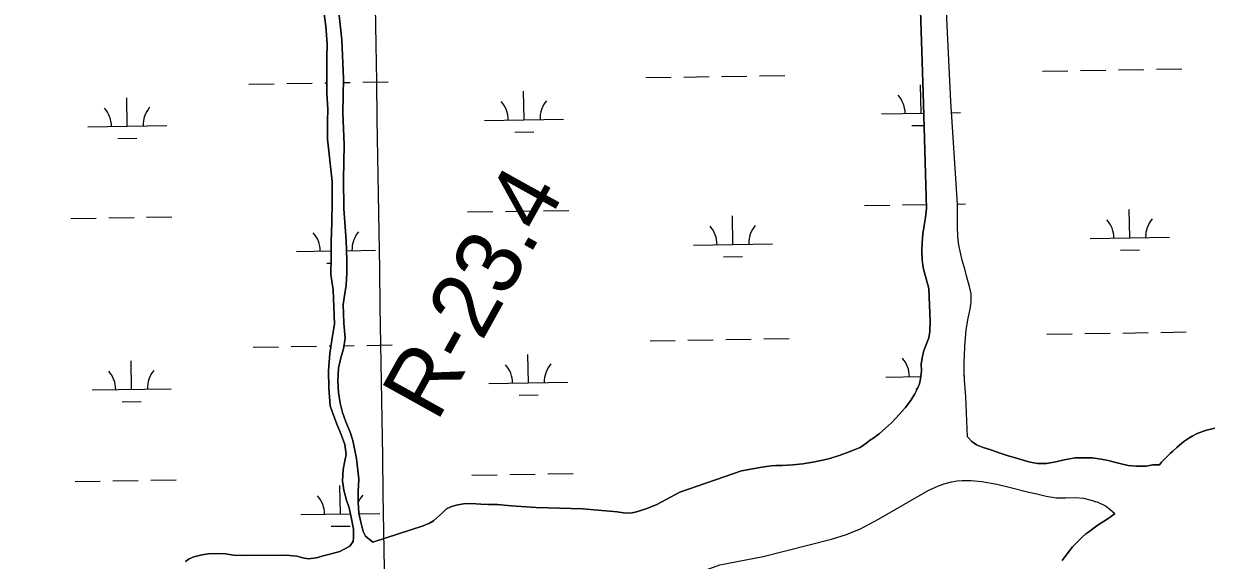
# Model space of a CAD drawing. Extents: x 3855477 to 3893699, y 299188 to 325115.
# Drawn here: x 3864404 to 3865905, y 316217 to 316895 of the extents above; entities that cross this region are included whole.
import ezdxf

# ---------------------------------------------------------------- set-up
doc = ezdxf.new("R2010")
doc.units = 0
for name, color, linetype in [('V-GRID-MAJR', 7, 'Continuous'), ('V-RIVR-EDGE', 7, 'Continuous'), ('V-RIVR-RANG-IDEN', 7, 'Continuous'), ('V-TOPO-SHOR', 7, 'Continuous'), ('V-WETL-SWMP', 7, 'Continuous')]:
    doc.layers.add(name, color=color, linetype=linetype)

msp = doc.modelspace()

# ---------------------------------------------------------------- linework, layer by layer
at = {"layer": 'V-GRID-MAJR'}
msp.add_spline([(3865044.1, 304703.3), (3864995.7, 307731.4), (3864898.7, 313791.5), (3864801.7, 319851.5), (3864753.2, 322883.5)], degree=3, dxfattribs=at)
at = {"layer": 'V-RIVR-EDGE'}
msp.add_spline([(3862579.1, 316706.6), (3862618.9, 316682.6), (3862652.8, 316666.1), (3862683, 316656.5), (3862696.2, 316652.9), (3862701.3, 316646.9), (3862715.3, 316640.1), (3862730, 316634.5), (3862738.8, 316633.6), (3862748.3, 316626.1), (3862763.5, 316620.4), (3862771, 316614.8), (3862792.5, 316606), (3862806.8, 316598.8), (3862818, 316594.4), (3862834.3, 316586.8), (3862853, 316578.4), (3862861.8, 316570.8), (3862880.1, 316564.8), (3862890, 316564.7), (3862900, 316564.3), (3862907.6, 316561.5), (3862923.9, 316554.7), (3862944.6, 316544.7), (3862975.6, 316529), (3863008.7, 316511), (3863036.9, 316493.4), (3863051.3, 316484.2), (3863059.6, 316479.8), (3863073.1, 316469.4), (3863078.7, 316461.8), (3863091, 316455.4), (3863113.7, 316446.6), (3863137.2, 316440.6), (3863166.3, 316430.5), (3863183.4, 316425.7), (3863207.7, 316412.1), (3863228, 316399.7), (3863238.3, 316395.7), (3863252.7, 316390.5), (3863259.4, 316385.3), (3863266.6, 316378.1), (3863269.4, 316370.9), (3863279.3, 316363.3), (3863294.4, 316355.7), (3863309.2, 316346.9), (3863343, 316331.3), (3863355.3, 316322.1), (3863380.4, 316304.5), (3863423.4, 316277.3), (3863452, 316258.5), (3863472.7, 316247.6), (3863532.4, 316214.8), (3863576.2, 316192.8), (3863612, 316174), (3863663, 316147.9), (3863702, 316129.9), (3863762.1, 316101.5), (3863803.5, 316080.6), (3863847.7, 316056.6), (3863876.3, 316044.2), (3863896.6, 316031.8), (3863917.7, 316020.6), (3863971.8, 315991.3), (3864020.8, 315966.1), (3864054.2, 315946.5), (3864091.6, 315926.9), (3864114.7, 315913.7), (3864131.9, 315906.9), (3864147, 315897.7), (3864174, 315883.6), (3864183.2, 315874.1), (3864194.3, 315870.4), (3864207.5, 315866.8), (3864224.2, 315858.8), (3864239.3, 315850.4), (3864262.4, 315840), (3864273.6, 315837.2), (3864288.7, 315830.4), (3864303.8, 315827.9), (3864315.4, 315825.1), (3864338.5, 315817.1), (3864360.8, 315810.6), (3864391.4, 315792.2), (3864418.9, 315776.2), (3864436, 315762.2), (3864459, 315741.9), (3864510.4, 315709.8), (3864535.4, 315695.8), (3864549, 315685.4), (3864561.3, 315675.8), (3864568.8, 315666.7), (3864582.4, 315656.7), (3864595.1, 315647.1), (3864600.7, 315641.1), (3864607, 315633.1), (3864612.6, 315626.3), (3864620.2, 315622.7), (3864637.3, 315615.9), (3864659.6, 315609), (3864678.3, 315601), (3864697.4, 315595.4), (3864745.6, 315571.8), (3864769.9, 315563.7), (3864787.4, 315555.7), (3864811.2, 315540.5), (3864821.2, 315537.7), (3864833.2, 315537.7), (3864842.3, 315536.5), (3864849.5, 315531.3), (3864857.4, 315522.9), (3864872.2, 315516.9), (3864908, 315506), (3864925.1, 315500.4), (3864937.9, 315498.8), (3864948.6, 315491.6), (3864957, 315489.5), (3864964.2, 315487.5), (3865017.5, 315468.3), (3865068.5, 315449.8), (3865096.3, 315439.4), (3865128.6, 315425), (3865154.9, 315414.9), (3865176, 315401.7), (3865212.2, 315385.7), (3865243.6, 315368.5), (3865263.1, 315356.5), (3865277.9, 315348.1), (3865297, 315338.1), (3865316.5, 315331.2), (3865337.2, 315318), (3865369.4, 315298.4), (3865405.2, 315275.2), (3865431.9, 315259.6), (3865448.2, 315254), (3865473.7, 315238.4), (3865499.1, 315224.8), (3865515.1, 315218), (3865531.8, 315209.2), (3865549.7, 315199.5), (3865571.2, 315191.5), (3865609, 315173.1), (3865654, 315145.5), (3865693.8, 315123.1), (3865732.8, 315101.8), (3865776.9, 315077.4), (3865798.4, 315063.8), (3865826.7, 315046.6), (3865853.4, 315032.6), (3865883.2, 315017.4), (3865895.1, 315011.4), (3865904.3, 315003.8), (3865913, 314994.6), (3865919.8, 314990.2), (3865927.8, 314987.4), (3865939.7, 314983.4), (3865950.5, 314980.6), (3865961.6, 314976.5), (3865977.5, 314967.3), (3866028.9, 314942.9), (3866056.7, 314928.5), (3866076.6, 314915.3), (3866096.5, 314901.7), (3866120.4, 314888.5), (3866143.9, 314878.1), (3866161.4, 314867.2), (3866178.1, 314862.8), (3866201.2, 314856.8), (3866223.1, 314850.4), (3866245.8, 314837.5), (3866263.7, 314827.1), (3866282.8, 314818.7), (3866292.4, 314818.7), (3866300.8, 314818.3), (3866309.9, 314816.3), (3866326.7, 314808.7), (3866348.5, 314791.1), (3866360.1, 314786.3), (3866377.6, 314778.6), (3866387.5, 314775), (3866394.3, 314767.4), (3866401.9, 314762.2), (3866413.8, 314757), (3866423.4, 314751.4), (3866432.1, 314749.8), (3866437.7, 314746.2), (3866445.6, 314739.4), (3866454.4, 314732.2), (3866485.5, 314719), (3866510.5, 314708.6), (3866533.2, 314691.4), (3866542, 314691.3), (3866549.9, 314690.9), (3866556.3, 314686.5), (3866561.9, 314678.5), (3866573.8, 314670.1), (3866598.9, 314663.7), (3866631.1, 314649.3), (3866660.6, 314640.4), (3866694.9, 314628.4), (3866748.2, 314604.4), (3866780.4, 314591.5), (3866811.1, 314575.5), (3866846.9, 314561.5), (3866895.5, 314539), (3866932.1, 314524.6), (3866954.8, 314513.4), (3866988.3, 314500.5), (3867018.5, 314486.5), (3867041.2, 314475.3), (3867068.7, 314458.5), (3867097.3, 314440.1), (3867124, 314432.5), (3867147.1, 314433.2), (3867169.4, 314428), (3867197.3, 314417.1), (3867215.2, 314410.7), (3867238.7, 314401.5), (3867251.4, 314396.3), (3867258.6, 314395.9), (3867271.4, 314397.4), (3867288.1, 314397.8), (3867302.4, 314396.1), (3867345.5, 314385.3), (3867427.5, 314359.6), (3867438.3, 314357.9), (3867445, 314357.9), (3867453.4, 314369.5), (3867458.2, 314381.4), (3867462.3, 314395.8), (3867462.3, 314404.1), (3867460.7, 314411.7), (3867457.1, 314414.1), (3867450.8, 314416.1), (3867442.8, 314416.5), (3867438.8, 314420.1), (3867443.2, 314422.1), (3867451.6, 314428.1), (3867458.8, 314437.2), (3867459.6, 314442.8), (3867460, 314450.8), (3867463.6, 314455.1), (3867470.8, 314463.9), (3867472, 314469.5), (3867472.4, 314477), (3867471.6, 314485), (3867465.7, 314504.5), (3867463.7, 314514.5), (3867463.4, 314524.5), (3867464.2, 314541.2), (3867469.1, 314571.1), (3867474.7, 314579.8), (3867478.3, 314581.4), (3867485, 314582.6), (3867525.3, 314574.9), (3867536, 314568.9), (3867545.2, 314565.7), (3867555.1, 314566.5), (3867569.9, 314566.1), (3867581, 314559.7), (3867585, 314552.1), (3867591.7, 314543.7), (3867611.6, 314532.9), (3867628, 314518.1), (3867650.2, 314493.3), (3867659.8, 314484.9), (3867663.3, 314473), (3867663.3, 314455.4), (3867660.1, 314447.5), (3867647.3, 314446.3), (3867632.2, 314444.7), (3867612.6, 314438.4), (3867582.3, 314425.3)], degree=3, dxfattribs=at)
at = {"layer": 'V-TOPO-SHOR'}
msp.add_line((3864836.2, 316247.2), (3864845.1, 316239.5), dxfattribs=at)
for points in [[(3865363.1, 316336.3), (3865376.5, 316337.2), (3865388.9, 316338.7), (3865401.8, 316340.6), (3865412.1, 316342.9), (3865423, 316345.4), (3865436.4, 316349.6), (3865447.8, 316353.6), (3865461.7, 316359.3), (3865469.8, 316365), (3865473.3, 316367.9), (3865478.8, 316371.6), (3865485.7, 316376.7), (3865493.7, 316383.5), (3865501, 316390.4), (3865507, 316396.8), (3865514.2, 316404.8), (3865518.8, 316409.7), (3865525.9, 316419.7), (3865530.8, 316427.2), (3865533.6, 316432.8), (3865536.5, 316439.8), (3865537.9, 316445.9), (3865539, 316456), (3865538.8, 316464.8), (3865540.1, 316472.7), (3865542, 316481.9), (3865545.4, 316490.5), (3865548.3, 316497.7), (3865549.5, 316506.1), (3865549.9, 316518.6), (3865548.2, 316560.1), (3865545, 316572.5), (3865541.4, 316586.5), (3865539.9, 316596.5), (3865539.6, 316607.9), (3865539.8, 316618.2), (3865540.8, 316629.4), (3865542.5, 316639.8), (3865544.2, 316650), (3865545.6, 316661.5), (3865541.4, 316808.2), (3865536.3, 316963.5)], [(3865597.2, 316372.9), (3865595.2, 316423.3), (3865593.6, 316444.5), (3865592.9, 316453.7), (3865592.9, 316466.7), (3865593.5, 316475.2), (3865593.7, 316487), (3865595.4, 316508.1), (3865598.3, 316522.9), (3865600.8, 316534.3), (3865601.9, 316543.2), (3865601.8, 316553.5), (3865599.7, 316563), (3865596.6, 316574.4), (3865593.7, 316585.3), (3865591.1, 316594.5), (3865589, 316603.6), (3865586.4, 316614.9), (3865585.2, 316625.7), (3865584.6, 316639), (3865584.6, 316666.9), (3865576.1, 316796.7), (3865568.8, 316954.4)], [(3864800.8, 316924.8), (3864806.3, 316874.8), (3864808.1, 316825.7), (3864807.3, 316782.5), (3864808.9, 316742.5), (3864808.6, 316719.6), (3864808.4, 316699), (3864808.8, 316660.9), (3864811.6, 316620.9), (3864812.5, 316596), (3864812.3, 316580.1), (3864811.4, 316564.7), (3864809.7, 316554), (3864807.6, 316540.2), (3864808.5, 316516.4), (3864810.3, 316497.4), (3864808.2, 316483.9), (3864804.9, 316472.5), (3864802, 316459.4), (3864801, 316443.6), (3864801.7, 316428.9), (3864803.9, 316415.5), (3864807, 316403.5), (3864811.2, 316391.6), (3864816.6, 316378.5), (3864820, 316368.2), (3864824.6, 316345.5), (3864827.5, 316319.4), (3864826.9, 316303.5), (3864826.8, 316290.1), (3864827.8, 316276.2), (3864830.1, 316264.7), (3864833.1, 316253.2), (3864836.2, 316247.2)], [(3864803.4, 316227.8), (3864816.1, 316234.4), (3864820.5, 316240.3), (3864821, 316245.5), (3864820.7, 316255.8), (3864818.5, 316268.9), (3864815.4, 316282.8), (3864812, 316292.7), (3864808.5, 316305.4), (3864807.1, 316317.3), (3864807.6, 316331.6), (3864810.1, 316342.6), (3864811.4, 316350.5), (3864809.9, 316363.2), (3864805.3, 316375.5), (3864799.9, 316388.7), (3864793.7, 316404.6), (3864791.4, 316412.1), (3864789.7, 316434.7), (3864789.1, 316456.1), (3864790.9, 316477.9), (3864793.5, 316494.9), (3864796.8, 316515.8), (3864795.3, 316558.6), (3864792.3, 316578), (3864792.6, 316599), (3864792.8, 316618.8), (3864793.4, 316643.8), (3864793.7, 316670.7), (3864794, 316695.7), (3864787.8, 316749.2), (3864788, 316772.2), (3864788.2, 316786.8), (3864787.2, 316807.4), (3864787, 316830.4), (3864787.2, 316851.4), (3864787.4, 316869.6), (3864785.7, 316891.8), (3864783.5, 316910.4)], [(3865597.2, 316372.9), (3865602.9, 316366.7), (3865608.7, 316362.5), (3865617.1, 316359.4), (3865626.7, 316356.1), (3865637.2, 316352.4), (3865648.6, 316348.9), (3865657.8, 316346), (3865666, 316343.6), (3865676.3, 316340.7), (3865685.9, 316338.9), (3865697.3, 316339.2), (3865708.8, 316341.3), (3865719.6, 316343.7), (3865733.5, 316346), (3865745, 316346.2), (3865754.9, 316346.1), (3865766.2, 316344.7), (3865775.2, 316342.9), (3865783.1, 316340.7), (3865791.7, 316338.4), (3865800.3, 316336.6), (3865810.8, 316335.6), (3865823, 316335.8), (3865831.7, 316337.2), (3865840.2, 316337.4)], [(3865840.2, 316337.4), (3865842.6, 316340.7), (3865846.7, 316345.1), (3865849.6, 316347.9), (3865853.9, 316352.2), (3865857.1, 316354.8), (3865861.8, 316359.4), (3865865.4, 316362.3), (3865871, 316366.8), (3865877.1, 316371.2), (3865881.3, 316373.6), (3865887.6, 316376.8), (3865895.8, 316379.7), (3865899.6, 316381), (3865904.9, 316382.4), (3865910.2, 316383.7)], [(3864845.1, 316239.5), (3864909.1, 316260.2), (3864917.1, 316263.6), (3864922.1, 316266.4), (3864933.7, 316277.1), (3864938.5, 316281.7), (3864943.9, 316284.2), (3864950.8, 316286.2), (3864959.8, 316288.1), (3864969.3, 316288.6), (3864981.9, 316287.8), (3864991.7, 316287.2), (3865003.1, 316287.4), (3865020.4, 316285.6), (3865052, 316283.6), (3865111, 316281.8), (3865154.1, 316277.9), (3865162.1, 316276.5), (3865166.8, 316276.2), (3865173.1, 316276.7), (3865178.9, 316277.9), (3865185.6, 316279.9), (3865192.9, 316282.4), (3865204.5, 316287.3), (3865233.3, 316302.6), (3865311.5, 316329.7), (3865337.2, 316334.4), (3865349.2, 316336.2), (3865354.8, 316336.4), (3865363.1, 316336.3)], [(3865547.4, 316304.8), (3865560.4, 316310.7), (3865569.1, 316313.8), (3865577.2, 316315.9), (3865584, 316317), (3865590.6, 316317.7), (3865601.7, 316317.7), (3865615.2, 316316.1), (3865634.5, 316313.1), (3865651.6, 316308.8), (3865675, 316302.9), (3865684.9, 316300.5), (3865696.9, 316297.6), (3865709.9, 316295.8), (3865721.3, 316295.8), (3865733.4, 316295.9), (3865743.9, 316295), (3865753.8, 316292.7), (3865761.9, 316290), (3865771.6, 316285.5), (3865777.4, 316281.4), (3865783.6, 316275.7)], [(3865196, 316176.5), (3865249.6, 316198.2), (3865283.9, 316210.8), (3865338.8, 316221.4), (3865425.3, 316243.4), (3865444.1, 316249.4), (3865454.5, 316253.6), (3865461.1, 316256.2), (3865467.4, 316259.3), (3865484.6, 316268.6), (3865547.4, 316304.8)], [(3865717.1, 316216.4), (3865720.6, 316221.5), (3865723.2, 316224.9), (3865727.3, 316230.3), (3865730.2, 316233.8), (3865735.1, 316238.9), (3865738.4, 316242), (3865741.9, 316245.3), (3865747.1, 316250.1), (3865750.8, 316252.6), (3865755.9, 316256.5), (3865759.3, 316259.1), (3865764.9, 316263), (3865769.1, 316265.8), (3865775, 316269.5), (3865778.9, 316271.9), (3865783.6, 316275.7)], [(3864608.3, 316215), (3864612.9, 316218.4), (3864618.9, 316221.1), (3864629.2, 316223.4), (3864637.5, 316224.9), (3864647.4, 316225.4), (3864659.2, 316224.8), (3864669.3, 316223.3), (3864680.4, 316222.6), (3864735.4, 316223.1), (3864749.1, 316221.9)], [(3864749.1, 316221.9), (3864756.8, 316219.7), (3864763.5, 316218.7), (3864774, 316219.8), (3864782.5, 316222.1), (3864792.5, 316224.8), (3864803.4, 316227.8)]]:
    msp.add_lwpolyline(points, dxfattribs=at)
at = {"layer": 'V-WETL-SWMP'}
for p, q in [((3865190.4, 316826.9), (3865222.4, 316827.4)), ((3865238.4, 316827.6), (3865270.4, 316828.2)), ((3865286.4, 316828.4), (3865318.4, 316828.9)), ((3865334.4, 316829.2), (3865366.4, 316829.7)), ((3865692.2, 316835), (3865724.2, 316835.6)), ((3865740.2, 316835.8), (3865772.2, 316836.3)), ((3865788.2, 316836.6), (3865820.2, 316837.1)), ((3865836.2, 316837.4), (3865868.2, 316837.9)), ((3864688.5, 316818.7), (3864720.5, 316819.2)), ((3864736.5, 316819.5), (3864768.5, 316820)), ((3864784.5, 316820.2), (3864787.1, 316820.3)), ((3864808, 316820.6), (3864816.5, 316820.8)), ((3864832.5, 316821), (3864864.5, 316821.5)), ((3865036.6, 316773.6), (3865036, 316809.6)), ((3865538.5, 316781.8), (3865537.9, 316817.8)), ((3864534.8, 316765.4), (3864534.2, 316801.4)), ((3865488.5, 316781), (3865542.1, 316781.8)), ((3865577.1, 316782.4), (3865588.5, 316782.6)), ((3864484.8, 316764.6), (3864584.8, 316766.2)), ((3864986.6, 316772.8), (3865086.6, 316774.4)), ((3865526.7, 316766.2), (3865542.6, 316766.4)), ((3864523, 316749.8), (3864547, 316750.2)), ((3865024.9, 316758), (3865048.9, 316758.4)), ((3865013.1, 316657.8), (3865045.1, 316658.3)), ((3865061.1, 316658.6), (3865093.1, 316659.1)), ((3865467, 316665.2), (3865499, 316665.7)), ((3865514.9, 316665.9), (3865545.5, 316666.4)), ((3865584.6, 316667.1), (3865594.9, 316667.3)), ((3865802.5, 316624.2), (3865801.9, 316660.2)), ((3864463.3, 316648.8), (3864495.3, 316649.3)), ((3864511.3, 316649.6), (3864543.3, 316650.1)), ((3864559.3, 316650.4), (3864591.3, 316650.9)), ((3864965.1, 316657), (3864997.1, 316657.5)), ((3865300.7, 316616), (3865300.1, 316652)), ((3865250.7, 316615.2), (3865350.7, 316616.8)), ((3865752.5, 316623.4), (3865852.5, 316625)), ((3864748.8, 316607), (3864792.6, 316607.7)), ((3864812.1, 316608.1), (3864848.8, 316608.7)), ((3865288.9, 316600.4), (3865312.9, 316600.8)), ((3865790.8, 316608.6), (3865814.8, 316609)), ((3864787.1, 316592.2), (3864792.5, 316592.3)), ((3865195.8, 316494.2), (3865227.8, 316494.7)), ((3865243.8, 316495), (3865275.8, 316495.5)), ((3865291.8, 316495.8), (3865323.8, 316496.3)), ((3865339.8, 316496.6), (3865371.8, 316497.1)), ((3865697.6, 316502.4), (3865729.6, 316502.9)), ((3865745.6, 316503.2), (3865777.6, 316503.7)), ((3865793.6, 316504), (3865825.6, 316504.5)), ((3865841.6, 316504.7), (3865873.6, 316505.3)), ((3864694, 316486.1), (3864726, 316486.6)), ((3864742, 316486.8), (3864773.9, 316487.4)), ((3864789.9, 316487.6), (3864792.4, 316487.7)), ((3864808.8, 316487.9), (3864821.9, 316488.1)), ((3864837.9, 316488.4), (3864869.9, 316488.9)), ((3865543.3, 316485.1), (3865543.3, 316485.1)), ((3864540.2, 316432.8), (3864539.6, 316468.8)), ((3865042.1, 316441), (3865041.5, 316477)), ((3865493.9, 316448.3), (3865538.3, 316449.1)), ((3865593.2, 316450), (3865593.9, 316450)), ((3864490.2, 316432), (3864590.2, 316433.6)), ((3864992.1, 316440.2), (3865092, 316441.8)), ((3865532.1, 316433.5), (3865533.9, 316433.6)), ((3865030.3, 316425.3), (3865054.3, 316425.7)), ((3864528.5, 316417.2), (3864552.5, 316417.6)), ((3864468.7, 316316.2), (3864500.7, 316316.7)), ((3864516.7, 316317), (3864548.7, 316317.5)), ((3864564.7, 316317.8), (3864596.7, 316318.3)), ((3864970.5, 316324.4), (3865002.5, 316324.9)), ((3865018.5, 316325.1), (3865050.5, 316325.7)), ((3865066.5, 316325.9), (3865098.5, 316326.4)), ((3864804.3, 316275.2), (3864803.7, 316311.2)), ((3865757.9, 316290.8), (3865759.5, 316290.8)), ((3864754.3, 316274.4), (3864817, 316275.4)), ((3864827.9, 316275.6), (3864854.2, 316276)), ((3864792.5, 316259.6), (3864816.5, 316260))]:
    msp.add_line(p, q, dxfattribs=at)
for points in [[(3865536.3, 316963.5), (3865541.4, 316808.2), (3865545.6, 316661.5), (3865544.2, 316650), (3865542.5, 316639.8), (3865540.8, 316629.4), (3865539.8, 316618.2), (3865539.6, 316607.9), (3865539.9, 316596.5), (3865541.4, 316586.5), (3865545, 316572.5), (3865548.2, 316560.1), (3865549.9, 316518.6), (3865549.5, 316506.1), (3865548.3, 316497.7), (3865545.4, 316490.5), (3865542, 316481.9), (3865540.1, 316472.7), (3865538.8, 316464.8), (3865539, 316456), (3865537.9, 316445.9), (3865536.5, 316439.8), (3865533.6, 316432.8), (3865530.8, 316427.2), (3865525.9, 316419.7), (3865518.8, 316409.7), (3865514.2, 316404.8), (3865507, 316396.8), (3865501, 316390.4), (3865493.7, 316383.5), (3865485.7, 316376.7), (3865478.8, 316371.6), (3865473.3, 316367.9), (3865469.8, 316365), (3865461.7, 316359.3), (3865447.8, 316353.6), (3865436.4, 316349.6), (3865423, 316345.4), (3865412.1, 316342.9), (3865401.8, 316340.6), (3865388.9, 316338.7), (3865376.5, 316337.2), (3865363.1, 316336.3), (3865354.8, 316336.4), (3865349.2, 316336.2), (3865337.2, 316334.4), (3865311.5, 316329.7), (3865233.3, 316302.6), (3865204.5, 316287.3), (3865192.9, 316282.4), (3865185.6, 316279.9), (3865178.9, 316277.9), (3865173.1, 316276.7), (3865166.8, 316276.2), (3865162.1, 316276.5), (3865154.1, 316277.9), (3865111, 316281.8), (3865052, 316283.6), (3865020.4, 316285.6), (3865003.1, 316287.4), (3864991.7, 316287.2), (3864981.9, 316287.8), (3864969.3, 316288.6), (3864959.8, 316288.1), (3864950.8, 316286.2), (3864943.9, 316284.2), (3864938.5, 316281.7), (3864933.7, 316277.1), (3864922.1, 316266.4), (3864917.1, 316263.6), (3864909.1, 316260.2), (3864845.1, 316239.5), (3864836.2, 316247.2), (3864833.1, 316253.2), (3864830.1, 316264.7), (3864827.8, 316276.2), (3864826.8, 316290.1), (3864826.9, 316303.5), (3864827.5, 316319.4), (3864824.6, 316345.5), (3864820.1, 316368.2), (3864816.6, 316378.5), (3864811.2, 316391.6), (3864807, 316403.5), (3864803.9, 316415.5), (3864801.7, 316428.9), (3864801, 316443.6), (3864802, 316459.4), (3864804.9, 316472.5), (3864808.2, 316483.9), (3864810.3, 316497.4), (3864808.5, 316516.4), (3864807.6, 316540.2), (3864809.7, 316554), (3864811.4, 316564.7), (3864812.3, 316580.1), (3864812.5, 316596), (3864811.6, 316620.9), (3864808.8, 316660.9), (3864808.4, 316699)], [(3865666, 316343.6), (3865657.8, 316346), (3865648.6, 316348.9), (3865637.2, 316352.4), (3865626.7, 316356.1), (3865617.1, 316359.4), (3865608.7, 316362.5), (3865602.9, 316366.7), (3865597.2, 316372.9), (3865595.2, 316423.3), (3865593.6, 316444.5), (3865592.9, 316453.7), (3865592.9, 316466.7), (3865593.5, 316475.2), (3865593.7, 316487), (3865595.4, 316508.1), (3865598.3, 316522.9), (3865600.8, 316534.3), (3865601.9, 316543.2), (3865601.8, 316553.5), (3865599.7, 316563), (3865596.6, 316574.4), (3865593.7, 316585.3), (3865591.1, 316594.5), (3865589, 316603.6), (3865586.4, 316614.9), (3865585.2, 316625.7), (3865584.6, 316639), (3865584.6, 316666.9), (3865576.1, 316796.7), (3865568.8, 316954.4)], [(3864808.4, 316699), (3864808.6, 316719.6), (3864808.9, 316742.5), (3864807.3, 316782.5), (3864808.1, 316825.7), (3864806.3, 316874.8), (3864800.8, 316924.8)], [(3864783.5, 316910.4), (3864785.7, 316891.8), (3864787.4, 316869.6), (3864787.2, 316851.4), (3864787, 316830.4), (3864787.2, 316807.4), (3864788.2, 316786.8), (3864788, 316772.2), (3864787.8, 316749.2), (3864794, 316695.7), (3864793.7, 316670.7), (3864793.4, 316643.8), (3864792.8, 316618.8), (3864792.6, 316599), (3864792.3, 316578), (3864795.3, 316558.6), (3864796.8, 316515.8), (3864793.5, 316494.9), (3864790.9, 316477.9), (3864789.1, 316456.1), (3864789.7, 316434.7), (3864791.4, 316412.1), (3864793.7, 316404.6), (3864799.9, 316388.7), (3864805.3, 316375.5), (3864809.9, 316363.2), (3864811.4, 316350.5), (3864810.1, 316342.6), (3864807.6, 316331.6), (3864807.1, 316317.3), (3864808.5, 316305.4), (3864812, 316292.7), (3864815.4, 316282.8), (3864818.5, 316268.9), (3864820.7, 316255.8), (3864821, 316245.5), (3864820.5, 316240.3), (3864816.1, 316234.4), (3864803.4, 316227.8), (3864792.5, 316224.8), (3864782.5, 316222.1), (3864774, 316219.8), (3864763.5, 316218.7), (3864756.8, 316219.7), (3864749.1, 316221.9), (3864735.4, 316223.1), (3864680.4, 316222.6), (3864669.3, 316223.3), (3864659.2, 316224.8), (3864647.4, 316225.4), (3864637.5, 316224.9)], [(3865910.2, 316383.7), (3865904.9, 316382.4), (3865899.6, 316381), (3865895.8, 316379.7), (3865887.6, 316376.8), (3865881.3, 316373.6), (3865877.1, 316371.2), (3865871, 316366.8), (3865865.4, 316362.3), (3865861.8, 316359.4), (3865857.1, 316354.8), (3865853.9, 316352.2), (3865849.6, 316347.9), (3865846.7, 316345.1), (3865842.6, 316340.7), (3865840.2, 316337.4), (3865831.7, 316337.2), (3865823, 316335.8), (3865810.8, 316335.6), (3865800.3, 316336.6), (3865791.7, 316338.4), (3865783.1, 316340.7), (3865775.2, 316342.9), (3865766.2, 316344.7), (3865754.9, 316346.1), (3865745, 316346.2), (3865733.5, 316346), (3865719.6, 316343.7), (3865708.8, 316341.3), (3865697.3, 316339.2), (3865685.9, 316338.9), (3865676.3, 316340.7), (3865666, 316343.6)], [(3865283.9, 316210.8), (3865338.8, 316221.4), (3865425.3, 316243.4), (3865444.1, 316249.4), (3865454.5, 316253.6), (3865461.1, 316256.2), (3865467.4, 316259.3), (3865484.6, 316268.6), (3865547.4, 316304.8), (3865560.4, 316310.7), (3865569.1, 316313.8), (3865577.2, 316315.9), (3865584, 316317), (3865590.6, 316317.7), (3865601.7, 316317.7), (3865615.2, 316316.1), (3865634.5, 316313.1), (3865651.6, 316308.8), (3865675, 316302.9), (3865684.9, 316300.5), (3865696.9, 316297.6), (3865709.9, 316295.8), (3865721.3, 316295.8), (3865733.4, 316295.9), (3865743.9, 316295), (3865753.8, 316292.7), (3865761.9, 316290), (3865771.6, 316285.5), (3865777.4, 316281.4), (3865783.6, 316275.7), (3865778.9, 316271.9), (3865775, 316269.5), (3865769.1, 316265.8), (3865764.9, 316263), (3865759.3, 316259.1), (3865755.9, 316256.5), (3865750.8, 316252.6), (3865747.1, 316250.1), (3865741.9, 316245.3), (3865738.4, 316242), (3865735.1, 316238.9), (3865730.2, 316233.8), (3865727.3, 316230.3), (3865723.2, 316224.9), (3865720.6, 316221.5), (3865717.1, 316216.4)], [(3864637.5, 316224.9), (3864629.2, 316223.4), (3864618.9, 316221.1), (3864612.9, 316218.4), (3864608.3, 316215)]]:
    msp.add_lwpolyline(points, dxfattribs=at)
for centre, start, end in [((3864981.4, 316773.2), 0.1615, 41.7052), ((3865091.9, 316775), 140.1615, 181.7052), ((3865483.2, 316781.4), 0.1615, 41.7052), ((3864479.6, 316765), 0.1615, 41.7052), ((3864590, 316766.8), 140.1615, 181.7052), ((3865747.3, 316623.8), 0.1615, 41.7052), ((3865857.7, 316625.6), 140.1615, 181.7052), ((3864743.6, 316607.4), 0.1615, 41.7052), ((3864854.1, 316609.2), 140.1615, 181.7052), ((3865245.4, 316615.6), 0.1615, 41.7052), ((3865355.9, 316617.4), 140.1615, 181.7052), ((3864986.8, 316440.5), 0.1615, 41.7052), ((3865097.3, 316442.3), 140.1615, 181.7052), ((3865488.6, 316448.7), 0.1615, 41.7052), ((3864485, 316432.4), 0.1615, 41.7052), ((3864595.4, 316434.2), 140.1615, 181.7052), ((3864749, 316274.8), 0.1615, 41.7052), ((3864859.5, 316276.6), 140.1615, 158.0272)]:
    msp.add_arc(centre, 35.2, start, end, dxfattribs=at)

# ---------------------------------------------------------------- texts
at = {"layer": 'V-RIVR-RANG-IDEN'}
msp.add_text('R-23.4', height=83, rotation=60.9627, dxfattribs=at).set_placement((3864926.3, 316390.1))

doc.saveas('drawing.dxf')
